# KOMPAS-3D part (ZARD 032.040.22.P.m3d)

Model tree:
1. Плоскость XY
2. Плоскость ZX
3. Плоскость ZY
4. Ось X
5. Ось Y
6. Ось Z
7. Начало координат
8. Булева операция:5
9. Булева операция:6
10. Булева операция:7
11. Булева операция:8
